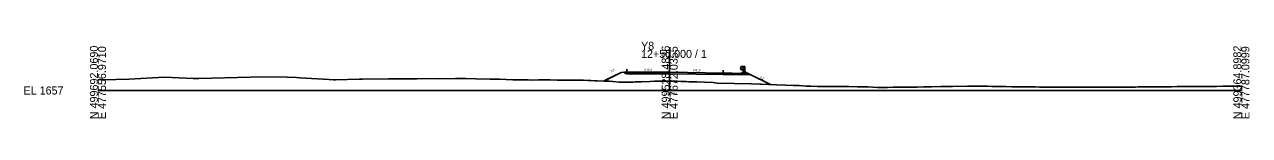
# Model space of a CAD drawing. Extents: x -26 to 403, y -10 to 2517.
# Drawn here: x -25.7 to 402.8, y 2490.3 to 2517 of the extents above; entities that cross this region are included whole.
import ezdxf

# ---------------------------------------------------------------- set-up
doc = ezdxf.new("R2010")
doc.units = 0
for name, color, linetype in [('Exist Cross Section Cell', 7, 'Continuous'), ('Exist XS Center Line Elevation Label', 7, 'Continuous'), ('Exist XS Ground Line', 7, 'Continuous'), ('Prop Road Sect_ Boring - Material (Outline)', 7, 'Continuous'), ('Prop XS Dump Level', 7, 'Continuous'), ('Prop XS Earthwork Shape', 7, 'Continuous'), ('Prop XS EOT Tick Mark', 7, 'Continuous'), ('Prop XS Finish Grade', 7, 'Continuous'), ('Prop XS Finish Grade CurbGutter', 7, 'Continuous'), ('Prop XS Finish Grade Earthwork', 7, 'Continuous'), ('Prop XS Finish Grade Paved Shoulder', 7, 'Continuous'), ('Prop XS Finish Grade Pavement', 7, 'Continuous'), ('Prop XS Guardrail', 7, 'Continuous'), ('Prop XS Hydro Fill Slope Data', 7, 'Continuous'), ('Prop XS Pvmt Edge Slope', 7, 'Continuous'), ('Prop XS SE Text', 7, 'Continuous'), ('Prop XS Side Slope Text', 7, 'Continuous'), ('Prop XS Subgrade CurbGutter', 7, 'Continuous'), ('Prop XS Subgrade Earthwork', 7, 'Continuous'), ('Scratch_Level_6', 7, 'Continuous')]:
    doc.layers.add(name, color=color, linetype=linetype)

msp = doc.modelspace()

# ---------------------------------------------------------------- linework, layer by layer
at = {"layer": 'Exist Cross Section Cell'}
for p, q in [((200, 2500), (200, 2514.15)), ((0, 2500), (200, 2500)), ((200, 2500), (400, 2500))]:
    msp.add_line(p, q, dxfattribs=at)
at = {"layer": 'Exist XS Ground Line'}
msp.add_lwpolyline([(0, 2503.65), (6.24, 2503.88), (10.81, 2503.94), (23.34, 2504.62), (33.29, 2504.21), (35.28, 2504.22), (53.37, 2504.64), (57.14, 2504.72), (66.2, 2504.68), (69.41, 2504.5), (70.59, 2504.39), (80.84, 2503.81), (82.44, 2503.72), (83.13, 2503.71), (91.4, 2503.93), (92.6, 2503.91), (101.67, 2504.06), (102.91, 2504.01), (104.19, 2504.02), (108.64, 2504.08), (110.14, 2504.02), (111.69, 2504.04), (115.82, 2504.12), (119.05, 2504.07), (125.13, 2504.19), (128.74, 2504.13), (132.23, 2504.07), (137.22, 2503.96), (140.42, 2503.91), (145.11, 2503.72), (147.89, 2503.69), (150.52, 2503.66), (151.99, 2503.55), (154.07, 2503.68), (156.29, 2503.66), (158.19, 2503.7), (160.69, 2503.62), (168.56, 2503.57), (169.9, 2503.55), (171.33, 2503.53), (172.39, 2503.43), (173.83, 2503.33), (174.22, 2503.33), (174.71, 2503.31), (178.94, 2503.24), (180.14, 2503.07), (182.3, 2502.87), (183.65, 2502.87), (185.78, 2502.92), (186.84, 2502.95), (187.22, 2502.94), (187.96, 2503), (190.1, 2503.02), (193.13, 2503.17), (194.72, 2503.2), (200.28, 2503.29), (201.21, 2503.27), (201.91, 2503.25), (202.67, 2503.22), (204.04, 2503.16), (204.41, 2503.14), (205.79, 2503.08), (206.73, 2503.04), (207.13, 2503.05), (207.65, 2502.99), (209.45, 2502.96), (212.2, 2502.86), (215.27, 2502.76), (216.59, 2502.59), (228.64, 2502.36), (243.44, 2501.69), (245.28, 2501.68), (247.73, 2501.55), (249.38, 2501.55), (251.71, 2501.4), (253.22, 2501.4), (254.86, 2501.4), (256.65, 2501.4), (258.84, 2501.39), (260.68, 2501.38), (262.67, 2501.38), (265.67, 2501.29), (267.49, 2501.29), (269.46, 2501.3), (272.69, 2501.04), (274.32, 2501.06), (276.15, 2501.08), (278.24, 2501.11), (284.52, 2501.15), (286.54, 2501.18), (288.85, 2501.22), (291.58, 2501.27), (294.89, 2501.34), (298.99, 2501.42), (304.24, 2501.52), (304.79, 2501.54), (305.54, 2501.55), (308.46, 2501.5), (309.23, 2501.49), (310.22, 2501.47), (311.18, 2501.45), (312.67, 2501.43), (313.31, 2501.42), (314.52, 2501.4), (315.19, 2501.39), (316.82, 2501.37), (317.55, 2501.35), (319.71, 2501.32), (320.28, 2501.31), (321.34, 2501.3), (321.78, 2501.29), (322.66, 2501.28), (323.28, 2501.28), (324.4, 2501.26), (326.29, 2501.24), (328.03, 2501.23), (329.37, 2501.21), (329.7, 2501.21), (330.49, 2501.2), (332.45, 2501.19), (334.81, 2501.18), (335.48, 2501.17), (337.01, 2501.17), (338.56, 2501.16), (339.18, 2501.16), (341.59, 2501.16), (343.51, 2501.16), (344.18, 2501.16), (344.65, 2501.16), (347.39, 2501.16), (347.85, 2501.16), (349.55, 2501.16), (350.76, 2501.16), (351.36, 2501.16), (352.23, 2501.16), (353.18, 2501.17), (353.84, 2501.17), (356.87, 2501.18), (358.55, 2501.19), (359.95, 2501.19), (360.91, 2501.2), (362.11, 2501.2), (362.99, 2501.21), (363.93, 2501.22), (365.26, 2501.23), (365.91, 2501.23), (366.48, 2501.23), (368, 2501.25), (369.57, 2501.27), (371.33, 2501.28), (372.53, 2501.29), (373.08, 2501.29), (373.83, 2501.31), (375.58, 2501.32), (377.51, 2501.33), (378.27, 2501.34), (380.16, 2501.35), (381.25, 2501.36), (382.09, 2501.36), (382.6, 2501.37), (384.4, 2501.38), (385.26, 2501.39), (386.93, 2501.39), (387.45, 2501.4), (389.01, 2501.42), (390.53, 2501.43), (390.85, 2501.43), (391.27, 2501.44), (393.56, 2501.46), (394.41, 2501.47), (395.64, 2501.48), (396.24, 2501.48), (396.64, 2501.49), (399.05, 2501.52), (400, 2501.53)], dxfattribs=at)
at = {"layer": 'Prop Road Sect_ Boring - Material (Outline)'}
for points in [[(185, 2506.42), (183.98, 2506.36), (184.46, 2505.88)], [(185, 2506.42), (184.46, 2505.88), (183.98, 2506.36)], [(225.58, 2506.26), (225.58, 2505.6), (226.79, 2505.6), (227.57, 2505.6), (228.2, 2505.6), (226.29, 2506.55)], [(225.58, 2506.26), (225.58, 2505.6), (226.79, 2505.6), (227.57, 2505.6), (228.2, 2505.6), (226.29, 2506.55)]]:
    msp.add_lwpolyline(points, close=True, dxfattribs=at)
at = {"layer": 'Prop XS Dump Level'}
for p, q in [((185, 2506.42), (200, 2506.36)), ((200, 2506.36), (218.69, 2506.06))]:
    msp.add_line(p, q, dxfattribs=at)
at = {"layer": 'Prop XS Earthwork Shape'}
msp.add_lwpolyline([(218.69, 2505.52), (221.92, 2505.48), (221.92, 2505.6), (227.57, 2505.6), (228.2, 2505.6), (235.28, 2502.06), (228.64, 2502.36), (216.59, 2502.59), (215.27, 2502.76), (212.2, 2502.86), (209.45, 2502.96), (207.65, 2502.99), (207.13, 2503.05), (206.73, 2503.04), (205.79, 2503.08), (204.41, 2503.14), (204.04, 2503.16), (202.67, 2503.22), (201.91, 2503.25), (201.21, 2503.27), (200.28, 2503.29), (194.72, 2503.2), (193.13, 2503.17), (190.1, 2503.02), (187.96, 2503), (187.22, 2502.94), (186.84, 2502.95), (185.78, 2502.92), (183.65, 2502.87), (182.3, 2502.87), (180.14, 2503.07), (178.94, 2503.24), (176.93, 2503.27), (183, 2506.31), (183.98, 2506.36), (184.46, 2505.88), (185, 2505.88), (185, 2505.81), (200, 2505.77)], close=True, dxfattribs=at)
at = {"layer": 'Prop XS EOT Tick Mark'}
for p, q in [((185, 2506.42), (185, 2507.42)), ((218.69, 2506.06), (218.69, 2507.06))]:
    msp.add_line(p, q, dxfattribs=at)
at = {"layer": 'Prop XS Finish Grade'}
for p, q in [((185, 2506.42), (183.98, 2506.36)), ((221.92, 2505.6), (221.92, 2505.48)), ((225.58, 2506.26), (226.29, 2506.55)), ((228.2, 2505.6), (226.29, 2506.55))]:
    msp.add_line(p, q, dxfattribs=at)
at = {"layer": 'Prop XS Finish Grade CurbGutter'}
for p, q in [((221.92, 2506.02), (224.74, 2505.92)), ((224.74, 2505.92), (225.58, 2506.26))]:
    msp.add_line(p, q, dxfattribs=at)
at = {"layer": 'Prop XS Finish Grade Earthwork'}
for p, q in [((183, 2506.31), (176.93, 2503.27)), ((183.98, 2506.36), (183, 2506.31)), ((228.2, 2505.6), (235.28, 2502.06))]:
    msp.add_line(p, q, dxfattribs=at)
at = {"layer": 'Prop XS Finish Grade Paved Shoulder'}
msp.add_line((218.69, 2506.06), (221.92, 2506.02), dxfattribs=at)
at = {"layer": 'Prop XS Finish Grade Pavement'}
for p, q in [((185, 2506.42), (200, 2506.36)), ((200, 2506.36), (218.69, 2506.06))]:
    msp.add_line(p, q, dxfattribs=at)
at = {"layer": 'Prop XS Guardrail'}
for p, q in [((224.78, 2508.12), (224.74, 2508.06)), ((224.74, 2508.06), (224.78, 2508)), ((224.78, 2507.51), (224.74, 2507.45)), ((224.74, 2507.45), (224.78, 2507.39)), ((225.13, 2508.32), (224.78, 2508.12)), ((224.78, 2508), (225.13, 2507.8)), ((225.13, 2507.71), (224.78, 2507.51)), ((224.78, 2507.39), (225.13, 2507.19)), ((225.74, 2508.32), (225.13, 2508.32)), ((225.13, 2507.8), (225.13, 2507.71)), ((225.13, 2507.19), (225.74, 2507.19)), ((226.35, 2508.32), (225.74, 2508.32)), ((225.74, 2508.32), (225.74, 2505.82)), ((226.35, 2505.82), (226.35, 2508.32))]:
    msp.add_line(p, q, dxfattribs=at)
at = {"layer": 'Prop XS Hydro Fill Slope Data'}
msp.add_line((183, 2506.31), (177.48, 2503.55), dxfattribs=at)
at = {"layer": 'Prop XS Pvmt Edge Slope'}
for p, q in [((185, 2506.42), (184.46, 2505.88)), ((225.58, 2505.6), (226.79, 2505.6)), ((226.79, 2505.6), (228.2, 2505.6))]:
    msp.add_line(p, q, dxfattribs=at)
at = {"layer": 'Prop XS Subgrade CurbGutter'}
for p, q in [((221.92, 2506.02), (221.92, 2505.6)), ((221.92, 2505.6), (225.58, 2505.6)), ((225.58, 2505.6), (225.58, 2506.26))]:
    msp.add_line(p, q, dxfattribs=at)
at = {"layer": 'Prop XS Subgrade Earthwork'}
for p, q in [((184.46, 2505.88), (183.98, 2506.36)), ((185, 2505.88), (184.46, 2505.88)), ((185, 2505.88), (185, 2505.81)), ((200, 2505.77), (185, 2505.81)), ((218.69, 2505.52), (200, 2505.77)), ((218.69, 2505.52), (221.92, 2505.48)), ((221.92, 2505.6), (227.57, 2505.6)), ((221.92, 2505.6), (221.92, 2505.48)), ((227.57, 2505.6), (228.2, 2505.6))]:
    msp.add_line(p, q, dxfattribs=at)
at = {"layer": 'Scratch_Level_6'}
msp.add_line((225.58, 2506.26), (225.58, 2505.6), dxfattribs=at)

# ---------------------------------------------------------------- texts
at = {"layer": 'Exist Cross Section Cell'}
for s, p in [('Y8', (190, 2514.15)), ('12+50.000 / 1', (190, 2511.35)), ('EL 1657', (-26, 2498.6))]:
    msp.add_text(s, height=2.8, dxfattribs=at).set_placement(p)
for s, p in [('N 499692.0690', (0, 2490)), ('E 477556.9710', (2.8, 2490)), ('N 499528.4836', (200, 2490)), ('E 477672.0355', (202.8, 2490)), ('N 499364.8982', (400, 2490)), ('E 477787.0999', (402.8, 2490))]:
    msp.add_text(s, height=2.8, rotation=90, dxfattribs=at).set_placement(p)
at = {"layer": 'Exist XS Center Line Elevation Label'}
msp.add_text('1660.29', height=0.9, dxfattribs=at).set_placement((197.96, 2498.39))
at = {"layer": 'Prop XS Dump Level'}
for p in [(183, 2506.27), (221.92, 2505.98)]:
    msp.add_text('Case1', height=0.04, dxfattribs=at).set_placement(p)
at = {"layer": 'Prop XS SE Text'}
for s, rotation, p in [('0.004', 359.7708, (191.2, 2506.89)), ('0.016', 359.0835, (208.16, 2506.73))]:
    msp.add_text(s, height=0.75, rotation=rotation, dxfattribs=at).set_placement(p)
at = {"layer": 'Prop XS Side Slope Text'}
for rotation, p in [(26.5651, (179.57, 2506.27)), (333.4349, (231.47, 2504.38))]:
    msp.add_text('2:1', height=0.75, rotation=rotation, dxfattribs=at).set_placement(p)

doc.saveas('drawing.dxf')
